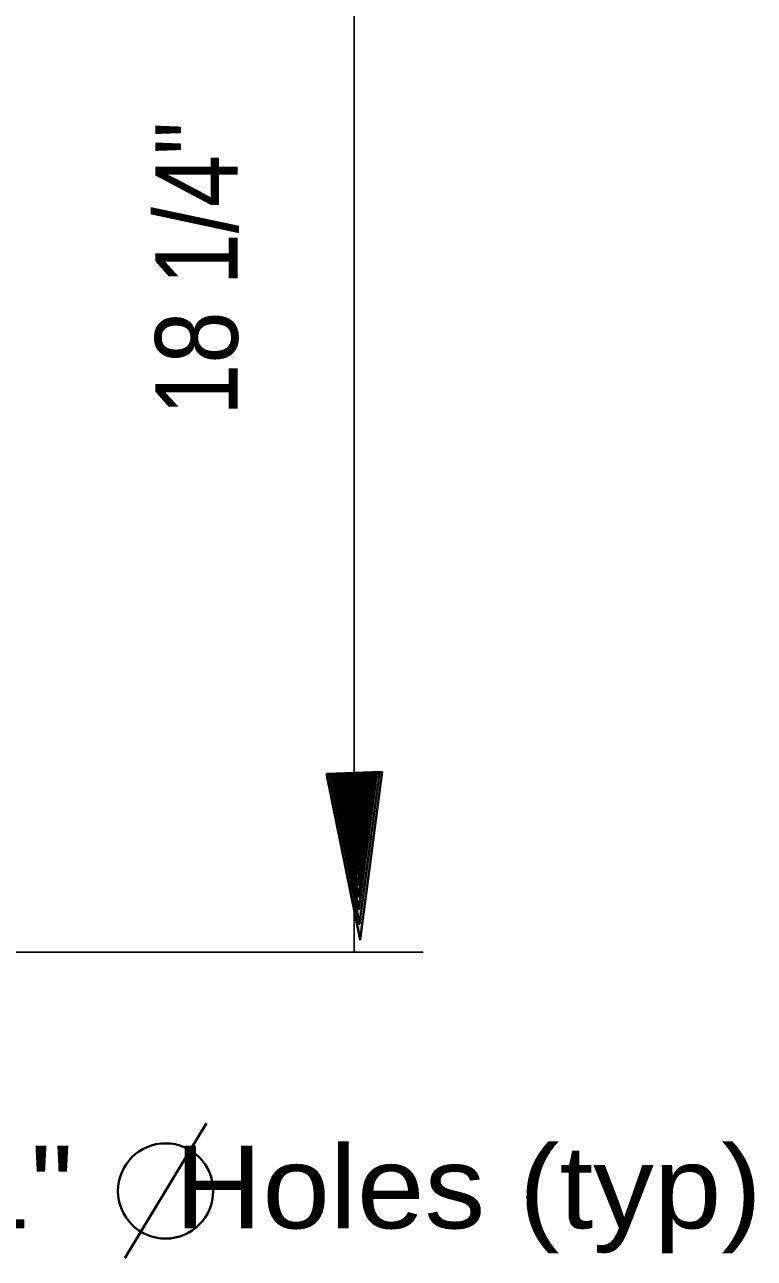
# Model space of a CAD drawing. Extents: x 895.6 to 930.4, y -2278.6 to -2254.7.
# Drawn here: x 904.118 to 905.254, y -2261.867 to -2259.945 of the extents above; entities that cross this region are included whole.
import ezdxf

# ---------------------------------------------------------------- set-up
doc = ezdxf.new("R2010")
doc.units = 0
doc.header["$LTSCALE"] = 0.051
doc.layers.add('1', color=7, linetype='Continuous', lineweight=70)
doc.layers.add('3', color=7, linetype='Continuous', lineweight=40)

msp = doc.modelspace()

# ---------------------------------------------------------------- hatches: boundary and pattern name
at = {"layer": '3'}
for points in [[(904.67433, -2261.10975), (904.58767, -2261.11267), (904.63983, -2261.37108), (904.63983, -2261.37108)], [(904.67, -2261.111), (904.592, -2261.11375), (904.639, -2261.34633), (904.639, -2261.34633)], [(904.66608, -2261.11225), (904.596, -2261.11458), (904.63825, -2261.32392), (904.63825, -2261.32392)], [(904.66267, -2261.11325), (904.59958, -2261.11542), (904.63758, -2261.30392), (904.63758, -2261.30392)], [(904.65967, -2261.11417), (904.60283, -2261.11608), (904.637, -2261.28583), (904.637, -2261.28583)], [(904.65675, -2261.11525), (904.60567, -2261.11683), (904.6365, -2261.26958), (904.6365, -2261.26958)], [(904.65417, -2261.11592), (904.60825, -2261.11742), (904.636, -2261.25483), (904.636, -2261.25483)], [(904.652, -2261.11675), (904.6105, -2261.118), (904.6355, -2261.24158), (904.6355, -2261.24158)], [(904.65, -2261.11717), (904.61258, -2261.1185), (904.635, -2261.22983), (904.635, -2261.22983)], [(904.648, -2261.11792), (904.61433, -2261.11908), (904.63467, -2261.219), (904.63467, -2261.219)], [(904.6465, -2261.11833), (904.61617, -2261.11942), (904.63442, -2261.20942), (904.63442, -2261.20942)], [(904.64492, -2261.11883), (904.61775, -2261.11983), (904.634, -2261.20083), (904.634, -2261.20083)], [(904.64358, -2261.11925), (904.61908, -2261.12008), (904.63375, -2261.19292), (904.63375, -2261.19292)], [(904.64233, -2261.11983), (904.62025, -2261.12033), (904.63358, -2261.186), (904.63358, -2261.186)], [(904.64125, -2261.12), (904.62142, -2261.12067), (904.63342, -2261.17975), (904.63342, -2261.17975)], [(904.64025, -2261.12042), (904.62242, -2261.12083), (904.63308, -2261.17408), (904.63308, -2261.17408)], [(904.63933, -2261.12058), (904.62325, -2261.12117), (904.63292, -2261.169), (904.63292, -2261.169)], [(904.6385, -2261.12075), (904.62408, -2261.12133), (904.63275, -2261.16442), (904.63275, -2261.16442)], [(904.63808, -2261.12117), (904.62492, -2261.12142), (904.63275, -2261.16033), (904.63275, -2261.16033)], [(904.6375, -2261.12133), (904.62567, -2261.12175), (904.63267, -2261.15667), (904.63267, -2261.15667)], [(904.637, -2261.12167), (904.62642, -2261.12208), (904.63283, -2261.15342), (904.63283, -2261.15342)], [(904.63642, -2261.12167), (904.627, -2261.12208), (904.63267, -2261.15033), (904.63267, -2261.15033)], [(904.63592, -2261.12183), (904.62742, -2261.12217), (904.63242, -2261.14758), (904.63242, -2261.14758)], [(904.6355, -2261.12208), (904.62792, -2261.12225), (904.6325, -2261.14525), (904.6325, -2261.14525)]]:
    msp.add_hatch(color=256, dxfattribs=at).paths.add_polyline_path(points)

# ---------------------------------------------------------------- linework, layer by layer
at = {"layer": '1', "lineweight": 25}
for p, q in [((904.63067, -2261.39058), (904.63067, -2258.93683)), ((903.45942, -2261.39058), (904.738, -2261.39058))]:
    msp.add_line(p, q, dxfattribs=at)
at = {"layer": '1', "lineweight": 40}
msp.add_line((904.40075, -2261.65683), (904.27333, -2261.86742), dxfattribs=at)
msp.add_circle((904.33703, -2261.7625), 0.07419, dxfattribs=at)
at = {"layer": '3'}
for points in [[(904.67433, -2261.10975), (904.58767, -2261.11267), (904.63983, -2261.37108), (904.63983, -2261.37108)], [(904.67, -2261.111), (904.592, -2261.11375), (904.639, -2261.34633), (904.639, -2261.34633)], [(904.66608, -2261.11225), (904.596, -2261.11458), (904.63825, -2261.32392), (904.63825, -2261.32392)], [(904.66267, -2261.11325), (904.59958, -2261.11542), (904.63758, -2261.30392), (904.63758, -2261.30392)], [(904.65967, -2261.11417), (904.60283, -2261.11608), (904.637, -2261.28583), (904.637, -2261.28583)], [(904.65675, -2261.11525), (904.60567, -2261.11683), (904.6365, -2261.26958), (904.6365, -2261.26958)], [(904.65417, -2261.11592), (904.60825, -2261.11742), (904.636, -2261.25483), (904.636, -2261.25483)], [(904.652, -2261.11675), (904.6105, -2261.118), (904.6355, -2261.24158), (904.6355, -2261.24158)], [(904.65, -2261.11717), (904.61258, -2261.1185), (904.635, -2261.22983), (904.635, -2261.22983)], [(904.648, -2261.11792), (904.61433, -2261.11908), (904.63467, -2261.219), (904.63467, -2261.219)], [(904.6465, -2261.11833), (904.61617, -2261.11942), (904.63442, -2261.20942), (904.63442, -2261.20942)], [(904.64492, -2261.11883), (904.61775, -2261.11983), (904.634, -2261.20083), (904.634, -2261.20083)], [(904.64358, -2261.11925), (904.61908, -2261.12008), (904.63375, -2261.19292), (904.63375, -2261.19292)], [(904.64233, -2261.11983), (904.62025, -2261.12033), (904.63358, -2261.186), (904.63358, -2261.186)], [(904.64125, -2261.12), (904.62142, -2261.12067), (904.63342, -2261.17975), (904.63342, -2261.17975)], [(904.64025, -2261.12042), (904.62242, -2261.12083), (904.63308, -2261.17408), (904.63308, -2261.17408)], [(904.63933, -2261.12058), (904.62325, -2261.12117), (904.63292, -2261.169), (904.63292, -2261.169)], [(904.6385, -2261.12075), (904.62408, -2261.12133), (904.63275, -2261.16442), (904.63275, -2261.16442)], [(904.63808, -2261.12117), (904.62492, -2261.12142), (904.63275, -2261.16033), (904.63275, -2261.16033)], [(904.6375, -2261.12133), (904.62567, -2261.12175), (904.63267, -2261.15667), (904.63267, -2261.15667)], [(904.637, -2261.12167), (904.62642, -2261.12208), (904.63283, -2261.15342), (904.63283, -2261.15342)], [(904.63642, -2261.12167), (904.627, -2261.12208), (904.63267, -2261.15033), (904.63267, -2261.15033)], [(904.63592, -2261.12183), (904.62742, -2261.12217), (904.63242, -2261.14758), (904.63242, -2261.14758)], [(904.6355, -2261.12208), (904.62792, -2261.12225), (904.6325, -2261.14525), (904.6325, -2261.14525)]]:
    msp.add_lwpolyline(points, close=True, dxfattribs=at)

# ---------------------------------------------------------------- texts
at = {"layer": '1', "width": 0.85}
msp.add_text('18 1/4"', height=0.1286, rotation=90, dxfattribs=at).set_placement((904.44942, -2260.55483))
at = {"layer": '1', "width": 1.1}
msp.add_text('1"   Holes (typ)', height=0.1286, dxfattribs=at).set_placement((904.02117, -2261.82075))

doc.saveas('drawing.dxf')
